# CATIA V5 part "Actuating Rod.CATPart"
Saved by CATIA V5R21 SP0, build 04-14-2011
Part number: Actuating Rod
Bounding box of the stored display mesh (mm): x -17.5 to 17.5, y -11.818 to 195.322, z -21 to 21
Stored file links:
  D:\CATIA V5R21 E-RESOURCES\CATIA-V5R21\catia-v5r21-Prts\c13_catia_v5r21_prt\c13_catia_v5r21_figr_13-41\Part & Asm files\Actuating Rod.CATPart
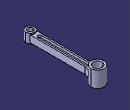
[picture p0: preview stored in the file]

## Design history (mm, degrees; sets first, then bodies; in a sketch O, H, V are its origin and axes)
Body1 (main body)
  Sketch1 on xy-plane, origin (0, 0, 0), H (1, 0, 0), V (0, 1, 0)
    arc A1 centre (0, 0) radius 12 from (-9, 7.9373) to (9, 7.9373) ccw
    arc A2 centre (0, 178) radius 17.5 from (13.5991, 166.9857) to (-13.5991, 166.9857) ccw
    point P1 (0, 178)
    line L1 (9, 154) -> (9, 7.9373)
    point P2 (9, 154)
    point P3 (9, 7.9373)
    arc A3 centre (29.6324, 154) radius 20.6324 from (9, 154) to (13.5991, 166.9857) cw
    point P5 (13.5991, 166.9857)
    point P6 (-13.5991, 166.9857)
    point P7 (-9, 154)
    arc A4 centre (-29.6324, 154) radius 20.6324 from (-9, 154) to (-13.5991, 166.9857) ccw
    point P9 (-9, 7.9373)
    line L2 (-9, 154) -> (-9, 7.9373)
    radius A2 = 17.5
    radius A1 = 12
    distance O P1 = 178
    distance V L1 = 9
    distance P1 P2 V = 24
    coincidence: P1 V
    vertical: L1 V
    tangency: A3 L1, A3 A2
    symmetry: P5 P6 V, P2 P7 V, A3 A4 V, P3 P9 V, L1 L2 V
  Pad1: profile Sketch1, direction (0, 0, 1), length 9, mirrored extent
  Sketch2 on xy-plane, origin (0, 0, 0), H (1, 0, 0), V (0, 1, 0)
    circle A1 centre (0, 0) radius 12
    reference projected arc E1 centre (0, 0) radius 12 from (-9, 7.9373) to (9, 7.9373) ccw from edge of Pad1
    reference projected arc E2 centre (0, 0) radius 12 from (-9, 7.9373) to (9, 7.9373) ccw from edge of Pad1
    reference projected arc E3 centre (0, 0) radius 12 from (-9, 7.9373) to (9, 7.9373) ccw from edge of Pad1
    concentricity: A1 E1, A1 E2
    tangency: A1 E3
  Pad2: profile Sketch2, direction (0, 0, 1), length 12, mirrored extent
  Sketch3 on xy-plane, origin (0, 0, 0), H (1, 0, 0), V (0, 1, 0)
    circle A1 centre (0, 178) radius 17.5
    point P1 (0, 178)
    reference projected arc E1 centre (0, 178) radius 17.5 from (13.5991, 166.9857) to (-13.5991, 166.9857) ccw from edge of Pad1
    reference projected arc E2 centre (0, 178) radius 17.5 from (13.5991, 166.9857) to (-13.5991, 166.9857) ccw from edge of Pad1
    coincidence: P1 V
    concentricity: A1 E1
    tangency: E2 A1
  Pad3: profile Sketch3, direction (0, 0, 1), length 21, mirrored extent
  Sketch4 on xy-plane, origin (0, 0, 0), H (1, 0, 0), V (0, 1, 0)
    circle A1 centre (0, 178) radius 12
    point P1 (0, 178)
    circle A2 centre (0, 0) radius 7.5
    reference projected circle E1 centre (0, 178) radius 17.5 from edge of Pad3
    radius A1 = 12
    radius A2 = 7.5
    coincidence: P1 V
    concentricity: A1 E1
  Pocket1: profile Sketch4, direction (0, 0, -1), length 21, mirrored extent
  Sketch5 on xy-plane, origin (0, 0, 0), H (1, 0, 0), V (0, 1, 0)
    construction line L1 (0, 24) -> (0, 154)
    point P1 (0, 24)
    line L2 (-5, 24) -> (-5, 154)
    line L3 (5, 154) -> (5, 24)
    arc A1 centre (0, 154) radius 5 from (-5, 154) to (5, 154) cw
    arc A2 centre (0, 24) radius 5 from (5, 24) to (-5, 24) cw
    length L1 = 130
    distance H P1 = 24
    radius A1 = 5
    coincidence: P1 V
    vertical: L1 V
    tangency: A1 L2, A2 L2, A1 L3, A2 L3
    parallelism: L1 L2
  Pocket2: profile Sketch5, direction (0, 0, -1), through (limit type 6), opposite side length -2.5
  Mirror1: of Pocket2, Sketch5, about xy-plane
